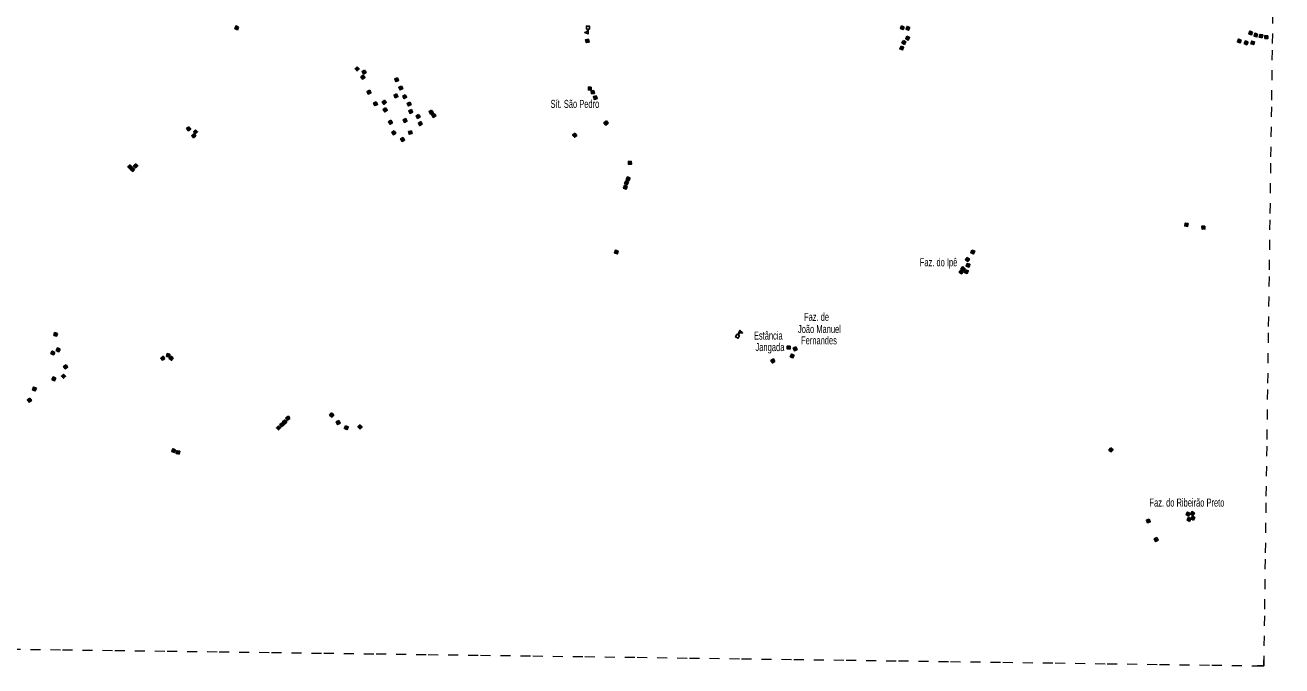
# Model space of a CAD drawing. Extents: x 679 to 705, y 7427.4 to 7455.4.
# Drawn here: x 692.24 to 704.8, y 7427.36 to 7433.76 of the extents above; entities that cross this region are included whole.
import ezdxf

# ---------------------------------------------------------------- set-up
doc = ezdxf.new("R2010")
doc.units = 0
doc.header["$LTSCALE"] = 0.032
doc.linetypes.add('SHORT_DASHED', pattern=[2.7, 1.5, -1.2])
for name, color, linetype, lineweight in [('2', 7, 'Continuous', 25), ('4', 7, 'Continuous', 25), ('58', 7, 'SHORT_DASHED', 13), ('63', 7, 'Continuous', 25)]:
    doc.layers.add(name, color=color, linetype=linetype, lineweight=lineweight)
doc.layers.add('61', color=7, linetype='Continuous')

msp = doc.modelspace()

# ---------------------------------------------------------------- hatches: boundary and pattern name
at = {"layer": '2'}
for points in [[(694.3718, 7433.7421), (694.359, 7433.716), (694.333, 7433.7288), (694.3457, 7433.7548)], [(701.0245, 7433.7428), (701.0128, 7433.7163), (700.9863, 7433.7279), (700.998, 7433.7545)], [(701.0807, 7433.7373), (701.0691, 7433.7107), (701.0425, 7433.7223), (701.0541, 7433.7488)], [(704.5071, 7433.6923), (704.4976, 7433.6648), (704.4702, 7433.6743), (704.4796, 7433.7017)], [(697.8678, 7433.6212), (697.874, 7433.5929), (697.8457, 7433.5867), (697.8395, 7433.615)], [(701.0171, 7433.6094), (701.0419, 7433.5945), (701.027, 7433.5697), (701.0021, 7433.5846)], [(701.0517, 7433.651), (701.0779, 7433.6387), (701.0657, 7433.6125), (701.0394, 7433.6247)], [(704.392, 7433.6118), (704.382, 7433.5845), (704.3548, 7433.5945), (704.3648, 7433.6218)], [(704.4616, 7433.5918), (704.449, 7433.5656), (704.4229, 7433.5782), (704.4354, 7433.6043)], [(704.5261, 7433.5951), (704.5186, 7433.567), (704.4906, 7433.5745), (704.498, 7433.6025)], [(704.557, 7433.6724), (704.5495, 7433.6444), (704.5215, 7433.6518), (704.5289, 7433.6798)], [(704.6083, 7433.6636), (704.6026, 7433.6351), (704.5742, 7433.6408), (704.5799, 7433.6693)], [(704.6598, 7433.6561), (704.6586, 7433.6271), (704.6296, 7433.6283), (704.6308, 7433.6573)], [(700.9927, 7433.5526), (701.019, 7433.5402), (701.0066, 7433.514), (700.9804, 7433.5264)], [(695.5576, 7433.3455), (695.577, 7433.3239), (695.5554, 7433.3045), (695.536, 7433.3261)], [(695.6311, 7433.3124), (695.6447, 7433.2868), (695.6191, 7433.2732), (695.6055, 7433.2987)], [(695.6175, 7433.2609), (695.6342, 7433.2372), (695.6105, 7433.2205), (695.5938, 7433.2442)], [(695.9586, 7433.2359), (695.9701, 7433.2093), (695.9434, 7433.1979), (695.932, 7433.2245)], [(695.6819, 7433.1108), (695.6932, 7433.0841), (695.6665, 7433.0728), (695.6552, 7433.0995)], [(695.9509, 7433.0745), (695.9634, 7433.0483), (695.9372, 7433.0359), (695.9247, 7433.0621)], [(695.9983, 7433.1534), (696.0113, 7433.1274), (695.9853, 7433.1145), (695.9724, 7433.1404)], [(696.0369, 7433.0664), (696.0509, 7433.041), (696.0255, 7433.027), (696.0115, 7433.0524)], [(697.8964, 7433.1432), (697.8964, 7433.1142), (697.8674, 7433.1142), (697.8674, 7433.1432)], [(697.9237, 7433.1085), (697.928, 7433.0798), (697.8993, 7433.0755), (697.895, 7433.1042)], [(697.9458, 7433.0569), (697.9554, 7433.0295), (697.928, 7433.0199), (697.9185, 7433.0473)], [(695.747, 7432.9958), (695.7597, 7432.9697), (695.7335, 7432.9571), (695.7209, 7432.9832)], [(695.8305, 7433.0107), (695.8479, 7432.9875), (695.8247, 7432.9701), (695.8073, 7432.9933)], [(695.8393, 7432.9347), (695.8563, 7432.9113), (695.8328, 7432.8943), (695.8158, 7432.9177)], [(696.0815, 7432.9934), (696.096, 7432.9683), (696.0709, 7432.9538), (696.0564, 7432.9789)], [(695.8939, 7432.8108), (695.9093, 7432.7863), (695.8848, 7432.7708), (695.8693, 7432.7954)], [(696.0428, 7432.8283), (696.0545, 7432.8018), (696.0279, 7432.7901), (696.0162, 7432.8166)], [(696.0984, 7432.9185), (696.1109, 7432.8923), (696.0847, 7432.8798), (696.0722, 7432.906)], [(696.1707, 7432.8697), (696.1852, 7432.8446), (696.1601, 7432.8301), (696.1456, 7432.8552)], [(696.3001, 7432.9132), (696.3145, 7432.8881), (696.2893, 7432.8737), (696.2749, 7432.8989)], [(696.3265, 7432.8796), (696.3413, 7432.8546), (696.3163, 7432.8399), (696.3015, 7432.8648)], [(698.0471, 7432.804), (698.0643, 7432.7806), (698.0409, 7432.7635), (698.0237, 7432.7869)], [(693.8736, 7432.7464), (693.8925, 7432.7243), (693.8705, 7432.7055), (693.8516, 7432.7275)], [(693.9237, 7432.6775), (693.9431, 7432.6559), (693.9216, 7432.6365), (693.9022, 7432.6581)], [(693.941, 7432.7169), (693.9615, 7432.6964), (693.941, 7432.6759), (693.9205, 7432.6964)], [(695.9265, 7432.7067), (695.9423, 7432.6823), (695.918, 7432.6665), (695.9022, 7432.6909)], [(696.0984, 7432.7058), (696.1053, 7432.6776), (696.0771, 7432.6707), (696.0703, 7432.6989)], [(696.1935, 7432.7979), (696.2076, 7432.7725), (696.1823, 7432.7585), (696.1682, 7432.7838)], [(697.7315, 7432.6817), (697.7507, 7432.66), (697.729, 7432.6408), (697.7098, 7432.6625)], [(696.0164, 7432.6389), (696.0304, 7432.6135), (696.0051, 7432.5995), (695.991, 7432.6248)], [(693.2861, 7432.3668), (693.3066, 7432.3463), (693.2861, 7432.3258), (693.2656, 7432.3463)], [(693.3308, 7432.3238), (693.3135, 7432.3005), (693.2902, 7432.3178), (693.3076, 7432.3411)], [(693.3413, 7432.3766), (693.3629, 7432.3572), (693.3435, 7432.3356), (693.3219, 7432.355)], [(698.2967, 7432.401), (698.2975, 7432.3721), (698.2685, 7432.3713), (698.2677, 7432.4003)], [(698.2681, 7432.1921), (698.2552, 7432.1662), (698.2292, 7432.1792), (698.2422, 7432.2051)], [(698.2848, 7432.2334), (698.2726, 7432.2071), (698.2463, 7432.2194), (698.2585, 7432.2457)], [(698.2557, 7432.1513), (698.2469, 7432.1237), (698.2193, 7432.1325), (698.228, 7432.1601)], [(703.8631, 7431.7791), (703.8578, 7431.7506), (703.8293, 7431.7559), (703.8346, 7431.7844)], [(704.0285, 7431.7545), (704.0303, 7431.7255), (704.0014, 7431.7237), (703.9995, 7431.7526)], [(698.1654, 7431.5047), (698.1573, 7431.4768), (698.1295, 7431.485), (698.1376, 7431.5128)], [(701.653, 7431.441), (701.6767, 7431.4244), (701.66, 7431.4006), (701.6363, 7431.4173)], [(701.7018, 7431.5141), (701.7289, 7431.5038), (701.7186, 7431.4767), (701.6915, 7431.4869)], [(701.5923, 7431.3171), (701.6147, 7431.2987), (701.5963, 7431.2763), (701.5739, 7431.2947)], [(701.6095, 7431.3495), (701.6316, 7431.3307), (701.6128, 7431.3086), (701.5907, 7431.3274)], [(701.6372, 7431.3184), (701.6641, 7431.3075), (701.6533, 7431.2806), (701.6264, 7431.2915)], [(701.6542, 7431.381), (701.6818, 7431.3722), (701.673, 7431.3446), (701.6454, 7431.3534)], [(692.5601, 7430.6825), (692.5523, 7430.6546), (692.5244, 7430.6624), (692.5322, 7430.6903)], [(699.8852, 7430.5554), (699.8852, 7430.5264), (699.8562, 7430.5264), (699.8562, 7430.5554)], [(699.9422, 7430.5469), (699.9535, 7430.5202), (699.9268, 7430.5089), (699.9155, 7430.5356)], [(692.5343, 7430.4924), (692.5207, 7430.4668), (692.4951, 7430.4805), (692.5087, 7430.5061)], [(692.5869, 7430.525), (692.5744, 7430.4988), (692.5483, 7430.5113), (692.5608, 7430.5375)], [(693.6337, 7430.4327), (693.6119, 7430.4135), (693.5927, 7430.4352), (693.6145, 7430.4544)], [(693.6854, 7430.474), (693.6793, 7430.4456), (693.651, 7430.4517), (693.6571, 7430.4801)], [(693.718, 7430.437), (693.7011, 7430.4134), (693.6775, 7430.4304), (693.6945, 7430.4539)], [(699.7318, 7430.401), (699.7065, 7430.3869), (699.6924, 7430.4123), (699.7177, 7430.4264)], [(699.9236, 7430.4641), (699.9118, 7430.4376), (699.8853, 7430.4494), (699.8971, 7430.4759)], [(692.6463, 7430.368), (692.6624, 7430.3438), (692.6383, 7430.3278), (692.6222, 7430.3519)], [(692.5447, 7430.2347), (692.5318, 7430.2087), (692.5058, 7430.2217), (692.5188, 7430.2477)], [(692.6216, 7430.2752), (692.6418, 7430.2544), (692.6211, 7430.2342), (692.6008, 7430.2549)], [(692.3494, 7430.1349), (692.3392, 7430.1078), (692.312, 7430.118), (692.3223, 7430.1452)], [(692.2848, 7430.0357), (692.3006, 7430.0113), (692.2763, 7429.9955), (692.2605, 7430.0199)], [(694.8068, 7429.7901), (694.8245, 7429.7671), (694.8016, 7429.7494), (694.7838, 7429.7723)], [(694.8334, 7429.8176), (694.8522, 7429.7956), (694.8301, 7429.7768), (694.8113, 7429.7989)], [(694.8849, 7429.8304), (694.8605, 7429.8148), (694.8449, 7429.8393), (694.8694, 7429.8548)], [(695.3011, 7429.8875), (695.3219, 7429.8673), (695.3017, 7429.8465), (695.2809, 7429.8667)], [(695.3731, 7429.8104), (695.3861, 7429.7845), (695.3601, 7429.7715), (695.3472, 7429.7975)], [(694.7708, 7429.7584), (694.791, 7429.7375), (694.7701, 7429.7174), (694.75, 7429.7383)], [(695.4394, 7429.7587), (695.4665, 7429.7484), (695.4562, 7429.7213), (695.4291, 7429.7316)], [(695.5861, 7429.769), (695.6052, 7429.7472), (695.5834, 7429.7281), (695.5643, 7429.7499)], [(703.0899, 7429.5382), (703.1118, 7429.5192), (703.0928, 7429.4973), (703.0709, 7429.5164)], [(693.7415, 7429.5178), (693.73, 7429.4912), (693.7034, 7429.5028), (693.7149, 7429.5294)], [(693.7821, 7429.5042), (693.7759, 7429.4759), (693.7475, 7429.4821), (693.7538, 7429.5104)], [(703.4729, 7428.8276), (703.484, 7428.8008), (703.4572, 7428.7897), (703.4461, 7428.8165)], [(703.8675, 7428.8576), (703.8423, 7428.8719), (703.8566, 7428.8972), (703.8818, 7428.8829)], [(703.8767, 7428.8044), (703.8514, 7428.8185), (703.8654, 7428.8438), (703.8908, 7428.8297)], [(703.886, 7428.8776), (703.9019, 7428.9019), (703.9261, 7428.886), (703.9103, 7428.8618)], [(703.9156, 7428.8177), (703.891, 7428.8329), (703.9062, 7428.8576), (703.9309, 7428.8423)], [(703.5496, 7428.6419), (703.5629, 7428.6161), (703.5372, 7428.6028), (703.5239, 7428.6286)]]:
    msp.add_hatch(color=256, dxfattribs=at).paths.add_polyline_path(points)

# ---------------------------------------------------------------- linework, layer by layer
for points in [[(694.3718, 7433.7421), (694.359, 7433.716), (694.333, 7433.7288), (694.3457, 7433.7548)], [(701.0245, 7433.7428), (701.0128, 7433.7163), (700.9863, 7433.7279), (700.998, 7433.7545)], [(701.0807, 7433.7373), (701.0691, 7433.7107), (701.0425, 7433.7223), (701.0541, 7433.7488)], [(704.5071, 7433.6923), (704.4976, 7433.6648), (704.4702, 7433.6743), (704.4796, 7433.7017)], [(697.8678, 7433.6212), (697.874, 7433.5929), (697.8457, 7433.5867), (697.8395, 7433.615)], [(701.0171, 7433.6094), (701.0419, 7433.5945), (701.027, 7433.5697), (701.0021, 7433.5846)], [(701.0517, 7433.651), (701.0779, 7433.6387), (701.0657, 7433.6125), (701.0394, 7433.6247)], [(704.392, 7433.6118), (704.382, 7433.5845), (704.3548, 7433.5945), (704.3648, 7433.6218)], [(704.4616, 7433.5918), (704.449, 7433.5656), (704.4229, 7433.5782), (704.4354, 7433.6043)], [(704.5261, 7433.5951), (704.5186, 7433.567), (704.4906, 7433.5745), (704.498, 7433.6025)], [(704.557, 7433.6724), (704.5495, 7433.6444), (704.5215, 7433.6518), (704.5289, 7433.6798)], [(704.6083, 7433.6636), (704.6026, 7433.6351), (704.5742, 7433.6408), (704.5799, 7433.6693)], [(704.6598, 7433.6561), (704.6586, 7433.6271), (704.6296, 7433.6283), (704.6308, 7433.6573)], [(700.9927, 7433.5526), (701.019, 7433.5402), (701.0066, 7433.514), (700.9804, 7433.5264)], [(695.5576, 7433.3455), (695.577, 7433.3239), (695.5554, 7433.3045), (695.536, 7433.3261)], [(695.6311, 7433.3124), (695.6447, 7433.2868), (695.6191, 7433.2732), (695.6055, 7433.2987)], [(695.6175, 7433.2609), (695.6342, 7433.2372), (695.6105, 7433.2205), (695.5938, 7433.2442)], [(695.9586, 7433.2359), (695.9701, 7433.2093), (695.9434, 7433.1979), (695.932, 7433.2245)], [(695.6819, 7433.1108), (695.6932, 7433.0841), (695.6665, 7433.0728), (695.6552, 7433.0995)], [(695.9509, 7433.0745), (695.9634, 7433.0483), (695.9372, 7433.0359), (695.9247, 7433.0621)], [(695.9983, 7433.1534), (696.0113, 7433.1274), (695.9853, 7433.1145), (695.9724, 7433.1404)], [(696.0369, 7433.0664), (696.0509, 7433.041), (696.0255, 7433.027), (696.0115, 7433.0524)], [(697.8964, 7433.1432), (697.8964, 7433.1142), (697.8674, 7433.1142), (697.8674, 7433.1432)], [(697.9237, 7433.1085), (697.928, 7433.0798), (697.8993, 7433.0755), (697.895, 7433.1042)], [(697.9458, 7433.0569), (697.9554, 7433.0295), (697.928, 7433.0199), (697.9185, 7433.0473)], [(695.747, 7432.9958), (695.7597, 7432.9697), (695.7335, 7432.9571), (695.7209, 7432.9832)], [(695.8305, 7433.0107), (695.8479, 7432.9875), (695.8247, 7432.9701), (695.8073, 7432.9933)], [(695.8393, 7432.9347), (695.8563, 7432.9113), (695.8328, 7432.8943), (695.8158, 7432.9177)], [(696.0815, 7432.9934), (696.096, 7432.9683), (696.0709, 7432.9538), (696.0564, 7432.9789)], [(695.8939, 7432.8108), (695.9093, 7432.7863), (695.8848, 7432.7708), (695.8693, 7432.7954)], [(696.0428, 7432.8283), (696.0545, 7432.8018), (696.0279, 7432.7901), (696.0162, 7432.8166)], [(696.0984, 7432.9185), (696.1109, 7432.8923), (696.0847, 7432.8798), (696.0722, 7432.906)], [(696.1707, 7432.8697), (696.1852, 7432.8446), (696.1601, 7432.8301), (696.1456, 7432.8552)], [(696.3001, 7432.9132), (696.3145, 7432.8881), (696.2893, 7432.8737), (696.2749, 7432.8989)], [(696.3265, 7432.8796), (696.3413, 7432.8546), (696.3163, 7432.8399), (696.3015, 7432.8648)], [(698.0471, 7432.804), (698.0643, 7432.7806), (698.0409, 7432.7635), (698.0237, 7432.7869)], [(693.8736, 7432.7464), (693.8925, 7432.7243), (693.8705, 7432.7055), (693.8516, 7432.7275)], [(693.9237, 7432.6775), (693.9431, 7432.6559), (693.9216, 7432.6365), (693.9022, 7432.6581)], [(693.941, 7432.7169), (693.9615, 7432.6964), (693.941, 7432.6759), (693.9205, 7432.6964)], [(695.9265, 7432.7067), (695.9423, 7432.6823), (695.918, 7432.6665), (695.9022, 7432.6909)], [(696.0984, 7432.7058), (696.1053, 7432.6776), (696.0771, 7432.6707), (696.0703, 7432.6989)], [(696.1935, 7432.7979), (696.2076, 7432.7725), (696.1823, 7432.7585), (696.1682, 7432.7838)], [(697.7315, 7432.6817), (697.7507, 7432.66), (697.729, 7432.6408), (697.7098, 7432.6625)], [(696.0164, 7432.6389), (696.0304, 7432.6135), (696.0051, 7432.5995), (695.991, 7432.6248)], [(693.2861, 7432.3668), (693.3066, 7432.3463), (693.2861, 7432.3258), (693.2656, 7432.3463)], [(693.3308, 7432.3238), (693.3135, 7432.3005), (693.2902, 7432.3178), (693.3076, 7432.3411)], [(693.3413, 7432.3766), (693.3629, 7432.3572), (693.3435, 7432.3356), (693.3219, 7432.355)], [(698.2967, 7432.401), (698.2975, 7432.3721), (698.2685, 7432.3713), (698.2677, 7432.4003)], [(698.2681, 7432.1921), (698.2552, 7432.1662), (698.2292, 7432.1792), (698.2422, 7432.2051)], [(698.2848, 7432.2334), (698.2726, 7432.2071), (698.2463, 7432.2194), (698.2585, 7432.2457)], [(698.2557, 7432.1513), (698.2469, 7432.1237), (698.2193, 7432.1325), (698.228, 7432.1601)], [(703.8631, 7431.7791), (703.8578, 7431.7506), (703.8293, 7431.7559), (703.8346, 7431.7844)], [(704.0285, 7431.7545), (704.0303, 7431.7255), (704.0014, 7431.7237), (703.9995, 7431.7526)], [(698.1654, 7431.5047), (698.1573, 7431.4768), (698.1295, 7431.485), (698.1376, 7431.5128)], [(701.653, 7431.441), (701.6767, 7431.4244), (701.66, 7431.4006), (701.6363, 7431.4173)], [(701.7018, 7431.5141), (701.7289, 7431.5038), (701.7186, 7431.4767), (701.6915, 7431.4869)], [(701.5923, 7431.3171), (701.6147, 7431.2987), (701.5963, 7431.2763), (701.5739, 7431.2947)], [(701.6095, 7431.3495), (701.6316, 7431.3307), (701.6128, 7431.3086), (701.5907, 7431.3274)], [(701.6372, 7431.3184), (701.6641, 7431.3075), (701.6533, 7431.2806), (701.6264, 7431.2915)], [(701.6542, 7431.381), (701.6818, 7431.3722), (701.673, 7431.3446), (701.6454, 7431.3534)], [(692.5601, 7430.6825), (692.5523, 7430.6546), (692.5244, 7430.6624), (692.5322, 7430.6903)], [(699.8852, 7430.5554), (699.8852, 7430.5264), (699.8562, 7430.5264), (699.8562, 7430.5554)], [(699.9422, 7430.5469), (699.9535, 7430.5202), (699.9268, 7430.5089), (699.9155, 7430.5356)], [(692.5343, 7430.4924), (692.5207, 7430.4668), (692.4951, 7430.4805), (692.5087, 7430.5061)], [(692.5869, 7430.525), (692.5744, 7430.4988), (692.5483, 7430.5113), (692.5608, 7430.5375)], [(693.6337, 7430.4327), (693.6119, 7430.4135), (693.5927, 7430.4352), (693.6145, 7430.4544)], [(693.6854, 7430.474), (693.6793, 7430.4456), (693.651, 7430.4517), (693.6571, 7430.4801)], [(693.718, 7430.437), (693.7011, 7430.4134), (693.6775, 7430.4304), (693.6945, 7430.4539)], [(699.7318, 7430.401), (699.7065, 7430.3869), (699.6924, 7430.4123), (699.7177, 7430.4264)], [(699.9236, 7430.4641), (699.9118, 7430.4376), (699.8853, 7430.4494), (699.8971, 7430.4759)], [(692.6463, 7430.368), (692.6624, 7430.3438), (692.6383, 7430.3278), (692.6222, 7430.3519)], [(692.5447, 7430.2347), (692.5318, 7430.2087), (692.5058, 7430.2217), (692.5188, 7430.2477)], [(692.6216, 7430.2752), (692.6418, 7430.2544), (692.6211, 7430.2342), (692.6008, 7430.2549)], [(692.3494, 7430.1349), (692.3392, 7430.1078), (692.312, 7430.118), (692.3223, 7430.1452)], [(692.2848, 7430.0357), (692.3006, 7430.0113), (692.2763, 7429.9955), (692.2605, 7430.0199)], [(694.8068, 7429.7901), (694.8245, 7429.7671), (694.8016, 7429.7494), (694.7838, 7429.7723)], [(694.8334, 7429.8176), (694.8522, 7429.7956), (694.8301, 7429.7768), (694.8113, 7429.7989)], [(694.8849, 7429.8304), (694.8605, 7429.8148), (694.8449, 7429.8393), (694.8694, 7429.8548)], [(695.3011, 7429.8875), (695.3219, 7429.8673), (695.3017, 7429.8465), (695.2809, 7429.8667)], [(695.3731, 7429.8104), (695.3861, 7429.7845), (695.3601, 7429.7715), (695.3472, 7429.7975)], [(694.7708, 7429.7584), (694.791, 7429.7375), (694.7701, 7429.7174), (694.75, 7429.7383)], [(695.4394, 7429.7587), (695.4665, 7429.7484), (695.4562, 7429.7213), (695.4291, 7429.7316)], [(695.5861, 7429.769), (695.6052, 7429.7472), (695.5834, 7429.7281), (695.5643, 7429.7499)], [(703.0899, 7429.5382), (703.1118, 7429.5192), (703.0928, 7429.4973), (703.0709, 7429.5164)], [(693.7415, 7429.5178), (693.73, 7429.4912), (693.7034, 7429.5028), (693.7149, 7429.5294)], [(693.7821, 7429.5042), (693.7759, 7429.4759), (693.7475, 7429.4821), (693.7538, 7429.5104)], [(703.4729, 7428.8276), (703.484, 7428.8008), (703.4572, 7428.7897), (703.4461, 7428.8165)], [(703.8675, 7428.8576), (703.8423, 7428.8719), (703.8566, 7428.8972), (703.8818, 7428.8829)], [(703.8767, 7428.8044), (703.8514, 7428.8185), (703.8654, 7428.8438), (703.8908, 7428.8297)], [(703.886, 7428.8776), (703.9019, 7428.9019), (703.9261, 7428.886), (703.9103, 7428.8618)], [(703.9156, 7428.8177), (703.891, 7428.8329), (703.9062, 7428.8576), (703.9309, 7428.8423)], [(703.5496, 7428.6419), (703.5629, 7428.6161), (703.5372, 7428.6028), (703.5239, 7428.6286)]]:
    msp.add_lwpolyline(points, close=True, dxfattribs=at)
at = {"layer": '4'}
for points in [[(697.8651, 7433.7227), (697.8645, 7433.6743), (697.8307, 7433.6863), (697.8598, 7433.6967), (697.8602, 7433.7228)], [(697.8602, 7433.7228), (697.8481, 7433.7229), (697.8484, 7433.7519), (697.8774, 7433.7516), (697.8771, 7433.7226), (697.8651, 7433.7227)], [(699.3664, 7430.6653), (699.3774, 7430.6601), (699.365, 7430.6339), (699.3388, 7430.6463), (699.3512, 7430.6725), (699.362, 7430.6674)], [(699.362, 7430.6674), (699.3827, 7430.7112), (699.4084, 7430.6862), (699.3776, 7430.6889), (699.3664, 7430.6653)]]:
    msp.add_lwpolyline(points, dxfattribs=at)
at = {"layer": '58'}
for points in [[(704.6209, 7427.3609), (704.6287, 7427.926), (704.6365, 7428.491), (704.6443, 7429.0561), (704.652, 7429.6212), (704.6598, 7430.1862), (704.6676, 7430.7513), (704.6754, 7431.3163), (704.6832, 7431.8814), (704.6909, 7432.4465), (704.6987, 7433.0115), (704.7065, 7433.5766), (704.7143, 7434.1416), (704.722, 7434.7067), (704.7298, 7435.2717), (704.7376, 7435.8368), (704.7453, 7436.4019), (704.7531, 7436.9669), (704.7608, 7437.532), (704.7686, 7438.097), (704.7764, 7438.6621), (704.7841, 7439.2271), (704.7919, 7439.7922), (704.7996, 7440.3572)], [(692.0899, 7427.5284), (692.612, 7427.5216), (693.1341, 7427.5148), (693.6562, 7427.508), (694.1783, 7427.5012), (694.7005, 7427.4944), (695.2226, 7427.4875), (695.7447, 7427.4806), (696.2668, 7427.4737), (696.7889, 7427.4668), (697.3111, 7427.4599), (697.8332, 7427.4529), (698.3553, 7427.446), (698.8774, 7427.439), (699.3996, 7427.432), (699.9217, 7427.425), (700.4438, 7427.4179), (700.966, 7427.4109), (701.4881, 7427.4038), (702.0102, 7427.3967), (702.5324, 7427.3896), (703.0545, 7427.3824), (703.5766, 7427.3753), (704.0988, 7427.3681), (704.6209, 7427.3609)]]:
    msp.add_lwpolyline(points, dxfattribs=at)
at = {"layer": '63'}
msp.add_lwpolyline([(704.5569, 7427.3609), (704.6185, 7427.3609), (704.6185, 7427.4216)], dxfattribs=at)

# ---------------------------------------------------------------- texts
at = {"layer": '61'}
for s, width, p in [('Sít. São Pedro', 0.7, (697.4893, 7432.9347)), ('Faz. do Ipê', 0.7, (701.1809, 7431.3527)), ('Faz. de ', 0.7, (700.023, 7430.807)), ('Estância', 0.7, (699.5224, 7430.62)), ('João Manuel', 0.7, (699.9627, 7430.6857)), ('Jangada', 0.65, (699.5374, 7430.5051)), ('Fernandes', 0.7, (699.9938, 7430.5726)), ('Faz. do Ribeirão Preto', 0.7, (703.4763, 7428.9521))]:
    msp.add_text(s, height=0.08, dxfattribs=dict(at, width=width)).set_placement(p)

doc.saveas('drawing.dxf')
